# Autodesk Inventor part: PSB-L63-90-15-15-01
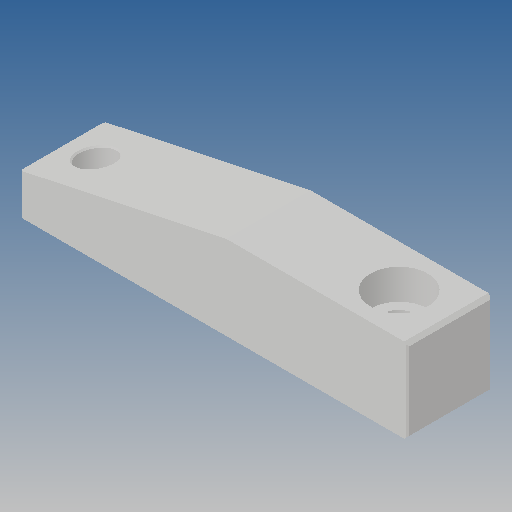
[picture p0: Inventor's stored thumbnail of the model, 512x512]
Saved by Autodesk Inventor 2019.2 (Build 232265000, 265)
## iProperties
Created: 2013-04
Part Number: PSB-L63-90-15-15-01
Material: Ogólny
Document SubType Name: Modeling
Designer: CADENGINEERING4
Density: 1 g/cm^3
Appearance: Domyślna
Author: CADENGINEERING4
Revision Number: ÈÎºÎ
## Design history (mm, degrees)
feature "µ¹½Ç1"
node "Bryła1"
